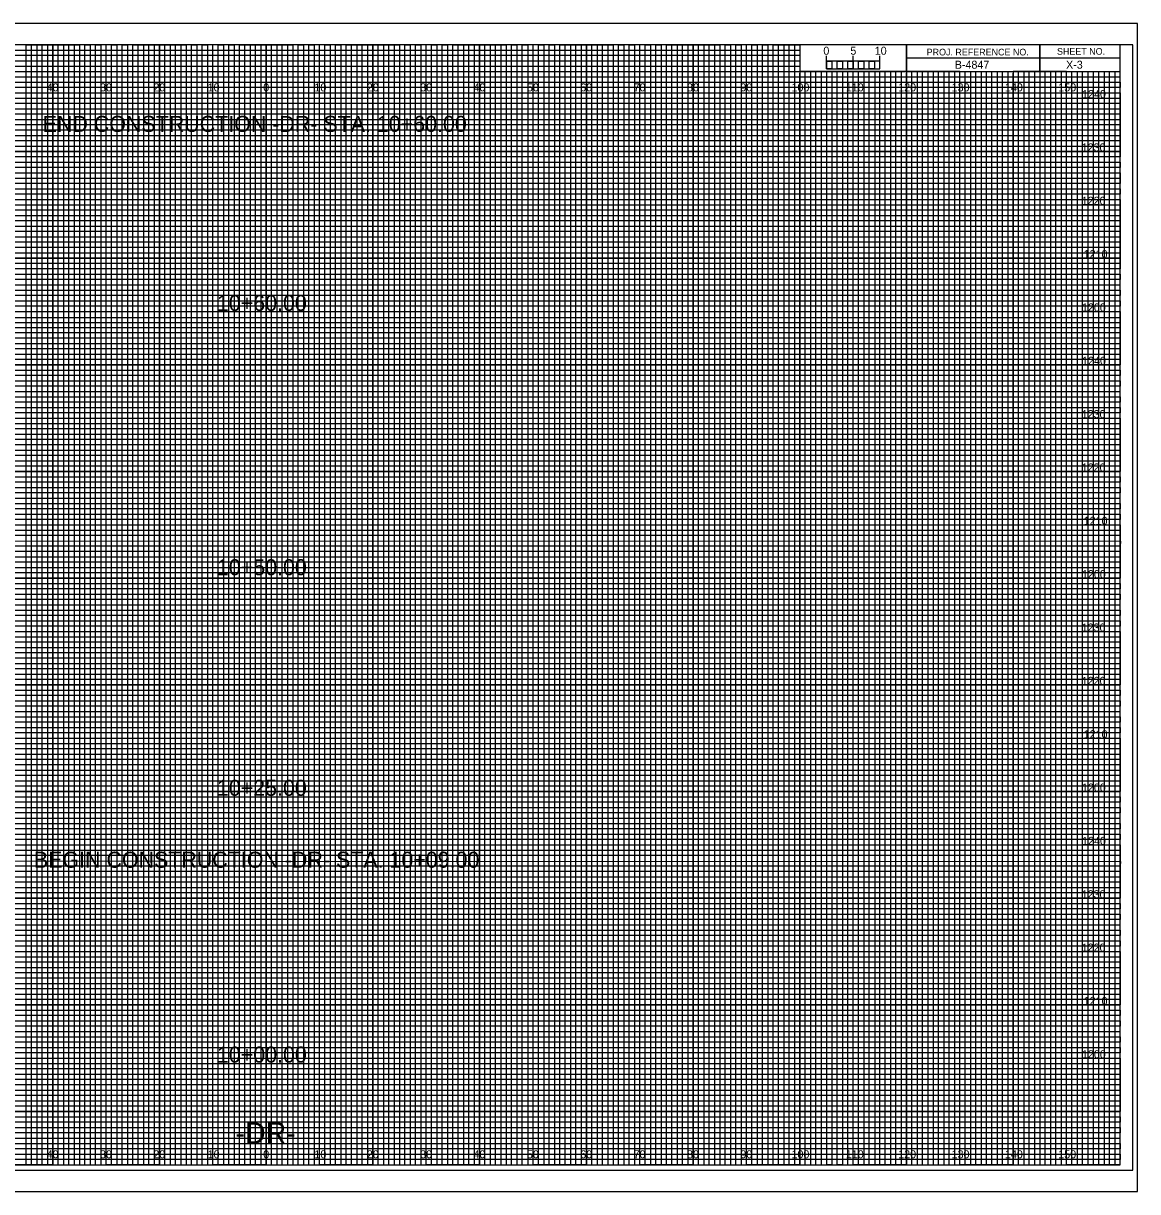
# Model space of a CAD drawing. Extents: x -13 to 323, y -5 to 214.
# Drawn here: x 114.5 to 323.3, y -5 to 214 of the extents above; entities that cross this region are included whole.
import ezdxf

# ---------------------------------------------------------------- set-up
doc = ezdxf.new("R2010")
doc.units = 0
for name, color, linetype in [('Default', 7, 'Continuous'), ('Prop XS Alignment Label', 7, 'Continuous'), ('Prop XS Bar Scale Labels', 7, 'Continuous'), ('Prop XS Elevation Labels', 7, 'Continuous'), ('Prop XS Offset Labels', 7, 'Continuous'), ('Prop XS Project Number', 7, 'Continuous'), ('Prop XS Sheet Number', 7, 'Continuous'), ('Prop XS Station Labels', 7, 'Continuous'), ('Sheet Cross Section CELL', 7, 'Continuous'), ('Sheet Cross Section Grid Major CELL', 7, 'Continuous'), ('Sheet Cross Section Grid Middle CELL', 7, 'Continuous'), ('Sheet Cross Section Grid Minor 1 CELL', 7, 'Continuous'), ('Sheet Cross Section Grid Minor 2 CELL', 7, 'Continuous'), ('Sheet Cross Section Scale CELL', 7, 'Continuous'), ('Sheet Cutting Line CELL', 7, 'Continuous'), ('Sheet DOT Grid CELL', 7, 'Continuous'), ('Sheet Plot Border Inside CELL', 7, 'Continuous'), ('Sheet Plot Border Outside CELL', 7, 'Continuous')]:
    doc.layers.add(name, color=color, linetype=linetype)

msp = doc.modelspace()

# ---------------------------------------------------------------- linework, layer by layer
at = {"layer": 'Sheet Cross Section CELL'}
for p, q in [((305, 210), (305, 205)), ((305, 205), (305, 210)), ((280, 207.5), (280, 205)), ((320, 207.49), (280, 207.49)), ((280, 205), (320, 205))]:
    msp.add_line(p, q, dxfattribs=at)
for points in [[(320, 210), (0, 210), (0, 0), (320, 0)], [(280, 210), (260, 210), (260, 205.03), (280, 205.03)], [(320, 210), (280, 210), (280, 205), (320, 205)]]:
    msp.add_lwpolyline(points, close=True, dxfattribs=at)
at = {"layer": 'Sheet Cross Section Grid Major CELL'}
for p, q in [((130, 210), (120, 210)), ((120, 210), (120, 0)), ((130, 0), (130, 210)), ((150, 210), (140, 210)), ((140, 210), (140, 0)), ((150, 0), (150, 210)), ((170, 210), (160, 210)), ((160, 210), (160, 0)), ((170, 0), (170, 210)), ((190, 210), (180, 210)), ((180, 210), (180, 0)), ((190, 0), (190, 210)), ((210, 210), (200, 210)), ((200, 210), (200, 0)), ((210, 0), (210, 210)), ((230, 210), (220, 210)), ((220, 210), (220, 0)), ((230, 0), (230, 210)), ((250, 210), (240, 210)), ((240, 210), (240, 0)), ((250, 0), (250, 210)), ((260, 210), (260, 0)), ((270, 0), (270, 205)), ((290, 205), (280, 205)), ((280, 205), (280, 0)), ((290, 0), (290, 205)), ((310, 205), (300, 205)), ((300, 205), (300, 0)), ((310, 0), (310, 205)), ((120, 0), (110, 0)), ((140, 0), (130, 0)), ((160, 0), (150, 0)), ((180, 0), (170, 0)), ((200, 0), (190, 0)), ((220, 0), (210, 0)), ((240, 0), (230, 0)), ((260, 0), (250, 0)), ((280, 0), (270, 0)), ((300, 0), (290, 0)), ((320, 0), (310, 0)), ((320, 0), (320, 0))]:
    msp.add_line(p, q, dxfattribs=at)
for points in [[(0, 200), (320, 200), (320, 190), (0, 190)], [(0, 180), (320, 180), (320, 170), (0, 170)], [(0, 160), (320, 160), (320, 150), (0, 150)], [(0, 140), (320, 140), (320, 130), (0, 130)], [(0, 120), (320, 120), (320, 110), (0, 110)], [(0, 100), (320, 100), (320, 90), (0, 90)], [(0, 80), (320, 80), (320, 70), (0, 70)], [(0, 60), (320, 60), (320, 50), (0, 50)], [(0, 40), (320, 40), (320, 30), (0, 30)], [(0, 20), (320, 20), (320, 10), (0, 10)]]:
    msp.add_lwpolyline(points, dxfattribs=at)
at = {"layer": 'Sheet Cross Section Grid Middle CELL'}
for points in [[(105, 0), (115, 0), (115, 210), (125, 210), (125, 0), (135, 0), (135, 210), (145, 210), (145, 0), (155, 0), (155, 210), (165, 210), (165, 0), (175, 0), (175, 210), (185, 210), (185, 0), (195, 0), (195, 210), (205, 210), (205, 0), (215, 0), (215, 210), (225, 210), (225, 0), (235, 0), (235, 210), (245, 210), (245, 0), (255, 0), (255, 210), (259.93, 210), (260, 210), (260, 205), (264.99, 205), (264.99, 0), (275, 0), (275, 205), (285, 205), (285, 0), (295, 0), (295, 205), (305, 205), (305, 0), (315, 0), (315, 205)], [(0, 205), (275, 205)], [(0, 185), (320, 185), (320, 195), (0, 195)], [(0, 165), (320, 165), (320, 175), (0, 175)], [(0, 145), (320, 145), (320, 155), (0, 155)], [(0, 125), (320, 125), (320, 135), (0, 135)], [(0, 105), (320, 105), (320, 115), (0, 115)], [(0, 85), (320, 85), (320, 95), (0, 95)], [(0, 65), (320, 65), (320, 75), (0, 75)], [(0, 45), (320, 45), (320, 55), (0, 55)], [(0, 25), (320, 25), (320, 35), (0, 35)], [(0, 5), (320, 5), (320, 15), (0, 15)]]:
    msp.add_lwpolyline(points, dxfattribs=at)
at = {"layer": 'Sheet Cross Section Grid Minor 1 CELL'}
for p, q in [((0, 209), (260, 209)), ((260, 209), (260, 207.98)), ((260, 207.98), (0, 207.98)), ((0, 207), (260, 207)), ((260, 205.89), (0, 205.89)), ((260, 207), (260, 205.89)), ((0, 204), (320, 204))]:
    msp.add_line(p, q, dxfattribs=at)
for points in [[(0, 203), (270, 203), (320, 203), (320, 202), (0, 202)], [(0, 201), (320, 201), (320, 199), (0, 199)], [(0, 198), (320, 198), (320, 197), (0, 196.98)], [(0, 196), (320, 196), (320, 194), (0, 194)], [(0, 193), (320, 193), (320, 192), (0, 192)], [(0, 191), (320, 191), (320, 189), (0, 189)], [(0, 188), (320, 188), (320, 187), (0, 187)], [(0, 186), (320, 186), (320, 184), (0, 184)], [(0, 183), (320, 183), (320, 182), (0, 182)], [(0, 181), (320, 181), (320, 179), (0, 179)], [(0, 178), (320, 178), (320, 177), (0, 177)], [(0, 176), (320, 176), (320, 173.95), (320, 173), (320, 172), (0, 172)], [(0, 174), (320, 174), (320, 173), (0, 173)], [(0, 171), (320, 171), (320, 169), (0, 169.03)], [(0, 169.03), (320, 169), (320, 168), (0, 168)], [(0, 167), (320, 167), (320, 166), (0, 166)], [(0, 164), (320, 164), (320, 163), (0, 163)], [(0, 162), (320, 162), (320, 161), (0, 161)], [(-0.07, 158.89), (320, 158.89), (320, 157.88), (-0.07, 157.88)], [(0, 157), (320, 157), (320, 156), (0, 156)], [(0, 154), (320, 154), (320, 153), (0, 153)], [(0, 152), (320, 152), (320, 151), (0, 151)], [(0, 149), (320, 149), (320, 148), (0, 148)], [(0, 147), (320, 147), (320, 146), (0, 146)], [(0, 144), (320, 144), (320, 143), (0, 143)], [(0, 142), (320, 142), (320, 141), (0, 141)], [(0, 139), (320, 139), (319.99, 137.98), (0, 138)], [(0, 137), (320, 137), (320, 136), (0, 136)], [(0, 134), (320, 134), (320, 133), (0, 133)], [(0, 132), (320, 132), (320, 131), (0, 131)], [(0, 129), (320, 129), (320, 128), (0, 128)], [(0, 127), (320, 127), (320, 126), (0, 126)], [(0, 124), (320, 124), (320, 123), (0, 123)], [(0, 122), (320, 122), (320, 121), (0, 121)], [(0, 119), (320, 119), (320, 118), (0, 118)], [(0, 116.99), (320.07, 116.91), (320, 116), (0, 116)], [(0, 114), (320, 114), (320, 113), (0, 113)], [(0, 112), (320, 112), (320, 111), (0, 111)], [(0, 109), (320, 109), (320, 108), (0, 108)], [(0, 107), (320, 107), (320, 106), (0, 106)], [(0, 104), (320, 104), (320, 103), (0, 103)], [(0, 102), (320, 102), (320, 101), (0, 101)], [(0, 99), (320, 99), (320, 98), (0, 98)], [(0, 97), (320, 97), (320, 96), (0, 96)], [(0, 94), (320, 94), (320, 93), (0, 93)], [(0, 92), (320, 92), (320, 91), (0, 91)], [(0, 89), (320, 89), (320, 88), (0, 88)], [(0, 87), (320, 87), (320, 86), (0, 86)], [(0, 84), (320, 84), (320, 83), (0, 83)], [(0, 82), (320, 82), (320, 81), (0, 81)], [(0, 79), (320, 79), (319.99, 77.98), (0, 78)], [(0, 77), (320, 77), (320, 76), (0, 76)], [(0, 74), (320, 74), (320, 73), (0, 73)], [(0, 72), (320, 72), (320, 71), (0, 71)], [(0, 69), (320, 69), (320, 68), (0, 68)], [(0, 67), (320, 67), (320, 66), (0, 66)], [(0, 64), (320, 64), (320, 63), (0, 63)], [(0, 62), (320, 62), (320, 61), (0, 61)], [(0, 59), (320, 59), (320, 58), (0, 58)], [(0, 56.99), (320.07, 56.91), (320, 56), (0, 56)], [(0, 54), (320, 54), (320, 53), (0, 53)], [(0, 52), (320, 52), (320, 51), (0, 51)], [(0, 49), (320, 49), (320, 48), (0, 48)], [(0, 47), (320, 47), (320, 46), (0, 46)], [(0, 44), (320, 44), (320, 43), (0, 43)], [(0, 42), (320, 42), (320, 41), (0, 41)], [(0, 39), (320, 39), (320, 38), (0, 38)], [(0, 37), (320, 37), (320, 36), (0, 36)], [(0, 34), (320, 34), (320, 33), (0, 33)], [(0, 32), (320, 32), (320, 31), (0, 31)], [(0, 29), (320, 29), (320, 28), (0, 28)], [(0, 27), (320, 27), (320, 26), (0, 26)], [(0, 24), (320, 24), (320, 23), (0, 23)], [(0, 22), (320, 22), (320, 21), (0, 21)], [(0, 19), (320, 19), (320, 18), (0, 18)], [(0, 17), (320, 17), (320, 16), (0, 16)], [(0, 14), (320, 14), (320, 13), (0, 13)], [(0, 12), (320, 12), (320, 11), (0, 11)], [(0, 9), (320, 9), (320, 8), (0, 8)], [(0, 7), (320, 7), (320, 6), (0, 6)], [(0, 4), (320, 4), (320, 3), (0, 3)], [(0, 2), (320, 2), (320, 1), (0, 1)]]:
    msp.add_lwpolyline(points, dxfattribs=at)
at = {"layer": 'Sheet Cross Section Grid Minor 2 CELL'}
for p, q in [((267, 205), (266.01, 205)), ((266.01, 205), (266.01, 0)), ((267, 0), (267, 205)), ((269, 205), (268, 205)), ((268, 205), (268, 0)), ((269, 0), (269, 205)), ((266.01, 0), (265, 0)), ((268, 0), (267, 0))]:
    msp.add_line(p, q, dxfattribs=at)
for points in [[(115, 0), (116, 0), (116, 210), (117, 210), (117, 0)], [(117, 0), (118, 0), (118, 210), (119, 210), (119, 0)], [(120, 0), (121, 0), (121, 210), (122, 210), (122, 0)], [(122, 0), (123, 0), (123, 210), (124, 210), (124, 0)], [(125, 0), (126, 0), (126, 210), (127, 210), (127, 0)], [(127, 0), (128, 0), (128, 210), (129, 210), (129, 0)], [(130, 0), (131, 0), (131, 210), (132, 210), (132, 0)], [(132, 0), (133, 0), (133, 210), (134, 210), (134, 0)], [(135, 0), (136, 0), (136, 210), (137, 210), (137, 0)], [(137, 0), (138, 0), (138, 210), (139, 210), (139, 0)], [(140, 0), (141, 0), (141, 210), (142, 210), (142, 0)], [(142, 0), (143, 0), (143, 210), (144, 210), (144, 0)], [(145, 0), (146, 0), (146, 210), (147, 210), (147, 0)], [(147, 0), (148, 0), (148, 210), (149, 210), (149, 0)], [(150, 0), (151, 0), (151, 210), (152, 210), (152, 0)], [(152, 0), (153, 0), (153, 210), (154, 210), (154, 0)], [(155, 0), (156, 0), (156, 210), (157, 210), (157, 0)], [(157, 0), (158, 0), (158, 210), (159, 210), (159, 0)], [(160, 0), (161, 0), (161, 210), (162, 210), (162, 0)], [(162, 0), (163, 0), (163, 210), (164, 210), (164, 0)], [(165, 0), (166, 0), (166, 210), (167, 210), (167, 0)], [(167, 0), (168, 0), (168, 210), (169, 210), (169, 0)], [(170, 0), (171, 0), (171, 210), (172, 210), (172, 0)], [(172, 0), (173, 0), (173, 210), (174, 210), (174, 0)], [(175, 0), (176, 0), (176, 210), (177, 210), (177, 0)], [(177, 0), (178, 0), (178, 210), (179, 210), (179, 0)], [(180, 0), (181, 0), (181, 210), (182, 210), (182, 0)], [(182, 0), (183, 0), (183, 210), (184, 210), (184, 0)], [(185, 0), (186, 0), (186, 210), (187, 210), (187, 0)], [(187, 0), (188, 0), (188, 210), (189, 210), (189, 0)], [(190, 0), (191, 0), (191, 210), (192, 210), (192, 0)], [(192, 0), (193, 0), (193, 210), (194, 210), (194, 0)], [(195, 0), (196, 0), (196, 210), (197, 210), (197, 0)], [(197, 0), (198, 0), (198, 210), (199, 210), (199, 0)], [(200, 0), (201, 0), (201, 210), (202, 210), (202, 0)], [(202, 0), (203, 0), (203, 210), (204, 210), (204, 0)], [(205, 0), (206, 0), (206, 210), (207, 210), (207, 0)], [(207, 0), (208, 0), (208, 210), (209, 210), (209, 0)], [(210, 0), (211, 0), (211, 210), (212, 210), (212, 0)], [(212, 0), (213, 0), (213, 210), (214, 210), (214, 0)], [(215, 0), (216, 0), (216, 210), (217, 210), (217, 0)], [(217, 0), (218, 0), (218, 210), (219, 210), (219, 0)], [(220, 0), (221, 0), (221, 210), (222, 210), (222, 0)], [(222, 0), (223, 0), (223, 210), (224, 210), (224, 0)], [(225, 0), (226, 0), (226, 210), (227, 210), (227, 0)], [(227, 0), (228, 0), (228, 210), (229, 210), (229, 0)], [(230, 0), (231, 0), (231, 210), (232, 210), (232, 0)], [(232, 0), (233, 0), (233, 210), (234, 210), (234, 0)], [(235, 0), (236, 0), (236, 210), (237, 210), (237, 0)], [(237, 0), (238, 0), (238, 210), (239, 210), (239, 0)], [(240, 0), (241, 0), (241, 210), (242, 210), (242, 0)], [(242, 0), (243, 0), (243, 210), (244, 210), (244, 0)], [(245, 0), (246, 0), (246, 210), (247, 210), (247, 0)], [(247, 0), (248, 0), (248, 210), (249, 210), (249, 0)], [(250, 0), (251, 0), (251, 210), (252, 210), (252, 0)], [(252, 0), (253, 0), (253, 210), (254, 210), (254, 0)], [(255, 0), (256, 0), (256, 210), (257, 210), (257, 0)], [(257, 0), (258, 0), (258, 210), (259, 210), (259, 0)], [(260, 0), (261, 0), (261, 205), (262.02, 205), (262.02, 0)], [(262, 0), (263, 0), (263, 205), (263.99, 205), (263.99, 0)], [(270, 0), (270.98, 0), (270.98, 205), (272, 205), (272, 0)], [(272, 0), (273, 0), (273, 205), (274.05, 205), (274.05, 0)], [(275, 0), (276, 0), (276, 205), (277, 205), (277, 0)], [(277, 0), (278, 0), (278, 205), (279, 205), (279, 0)], [(280, 0), (281, 0), (281, 205), (282, 205), (282, 0)], [(282, 0), (283, 0), (283, 205), (284, 205), (284, 0)], [(285, 0), (286, 0), (286, 205), (287, 205), (287, 0)], [(287, 0), (288, 0), (288, 205), (289, 205), (289, 0)], [(290, 0), (291, 0), (291, 205), (292, 205), (292, 0)], [(292, 0), (293, 0), (293, 205), (294, 205), (294, 0)], [(295, 0), (296, 0), (296, 205), (297, 205), (297, 0)], [(297, 0), (298, 0), (298, 205), (299, 205), (299, 0)], [(300, 0), (301, 0), (301, 205), (302, 205), (302, 0)], [(302, 0), (303, 0), (303, 205), (304, 205), (304, 0)], [(305, 0), (306, 0), (306, 205), (307, 205), (307, 0)], [(307, 0), (308, 0), (308, 205), (309, 205), (309, 0)], [(310, 0), (311, 0), (311, 205), (312, 205), (312, 0)], [(312, 0), (313, 0), (313, 205), (314, 205), (314, 0)], [(315, 0), (316, 0), (316, 205), (317, 205), (317, 0)], [(317, 0), (318, 0), (318, 205), (319, 205), (319, 0)]]:
    msp.add_lwpolyline(points, dxfattribs=at)
at = {"layer": 'Sheet Cross Section Scale CELL'}
for p, q in [((265, 205.49), (265, 207.9)), ((265, 206.9), (265, 207.9)), ((270, 205.49), (270, 207.9)), ((275, 205.49), (275, 207.9)), ((275, 206.9), (275, 207.9))]:
    msp.add_line(p, q, dxfattribs=at)
for points in [[(275, 206.9), (265, 206.9), (265, 205.49), (275, 205.49)], [(265, 206.9), (266, 206.9), (266, 205.49), (265, 205.49)], [(267, 206.9), (268, 206.9), (268, 205.49), (267, 205.49)], [(269, 206.9), (270, 206.9), (270, 205.49), (269, 205.49)], [(271, 206.9), (272, 206.9), (272, 205.49), (271, 205.49)], [(273, 206.9), (274, 206.9), (274, 205.49), (273, 205.49)]]:
    msp.add_lwpolyline(points, close=True, dxfattribs=at)
at = {"layer": 'Sheet Cutting Line CELL'}
for p, q in [((323.3, 214), (-13.4, 214)), ((-13.4, -5), (323.3, -5))]:
    msp.add_line(p, q, dxfattribs=at)
at = {"layer": 'Sheet DOT Grid CELL'}
for p, q in [((120, 0), (120, 210)), ((130, 0), (130, 210)), ((140, 0), (140, 210)), ((150, 0), (150, 210)), ((160, 0), (160, 210)), ((170, 0), (170, 210)), ((180, 0), (180, 210)), ((190, 0), (190, 210)), ((200, 0), (200, 210)), ((210, 0), (210, 210)), ((220, 0), (220, 210)), ((230, 0), (230, 210)), ((240, 0), (240, 210)), ((250, 0), (250, 210)), ((260, 0), (260, 204.69)), ((270, 0), (270, 204.69)), ((280, 0), (280, 204.69)), ((290, 0), (290, 204.69)), ((300, 0), (300, 204.69)), ((310, 0), (310, 204.69)), ((0, 200), (320, 200)), ((0, 190), (320, 190)), ((0, 180), (320, 180)), ((0, 170), (320, 170)), ((0, 160), (320, 160)), ((0, 150), (320, 150)), ((0, 140), (320, 140)), ((0, 130), (320, 130)), ((0, 120), (320, 120)), ((0, 110), (320, 110)), ((0, 100), (320, 100)), ((0, 90), (320, 90)), ((0, 80), (320, 80)), ((0, 70), (320, 70)), ((0, 60), (320, 60)), ((0, 50), (320, 50)), ((0, 40), (320, 40)), ((0, 30), (320, 30)), ((0, 20), (320, 20)), ((0, 10), (320, 10))]:
    msp.add_line(p, q, dxfattribs=at)
at = {"layer": 'Sheet Plot Border Inside CELL'}
msp.add_lwpolyline([(-10.8, -1), (322.4, -1), (322.4, 210), (-10.8, 210)], close=True, dxfattribs=at)
at = {"layer": 'Sheet Plot Border Outside CELL'}
msp.add_lwpolyline([(-13.4, -5), (323.3, -5), (323.3, 214), (-13.4, 214)], close=True, dxfattribs=at)

# ---------------------------------------------------------------- texts
at = {"layer": 'Default'}
for s, p in [('END CONSTRUCTION -DR- STA. 10+60.00', (118.12, 193.66)), ('BEGIN CONSTRUCTION -DR- STA. 10+09.00', (116.47, 55.72))]:
    msp.add_text(s, height=3, dxfattribs=at).set_placement(p)
at = {"layer": 'Prop XS Alignment Label'}
msp.add_text('-DR-', height=4, dxfattribs=at).set_placement((154.25, 4))
at = {"layer": 'Prop XS Bar Scale Labels'}
for s, p in [('5', (269.47, 208.12)), ('10', (274.04, 208.12))]:
    msp.add_text(s, height=1.5, dxfattribs=at).set_placement(p)
at = {"layer": 'Prop XS Elevation Labels'}
for s, p in [('1240', (312.9, 200)), ('1230', (312.82, 190)), ('1220', (312.83, 180)), ('1210', (313.2, 170)), ('1200', (312.87, 160)), ('1240', (312.9, 150)), ('1230', (312.82, 140)), ('1220', (312.83, 130)), ('1210', (313.2, 120)), ('1200', (312.87, 110)), ('1230', (312.82, 100)), ('1220', (312.83, 90)), ('1210', (313.2, 80)), ('1200', (312.87, 70)), ('1240', (312.9, 60)), ('1230', (312.82, 50)), ('1220', (312.83, 40)), ('1210', (313.2, 30)), ('1200', (312.87, 20))]:
    msp.add_text(s, height=1.5, dxfattribs=at).set_placement(p)
at = {"layer": 'Prop XS Offset Labels'}
for s, p in [('40', (118.86, 201.25)), ('30', (128.86, 201.25)), ('20', (138.86, 201.25)), ('10', (149.04, 201.25)), ('0', (159.45, 201.25)), ('0', (159.45, 201.25)), ('10', (169.04, 201.25)), ('20', (178.86, 201.25)), ('30', (188.86, 201.25)), ('40', (198.86, 201.25)), ('50', (208.86, 201.25)), ('60', (218.86, 201.25)), ('70', (228.86, 201.25)), ('80', (238.86, 201.25)), ('90', (248.86, 201.25)), ('100', (258.44, 201.25)), ('110', (268.62, 201.25)), ('120', (278.44, 201.25)), ('130', (288.44, 201.25)), ('140', (298.44, 201.25)), ('150', (308.44, 201.25)), ('40', (118.86, 1.25)), ('30', (128.86, 1.25)), ('20', (138.86, 1.25)), ('10', (149.04, 1.25)), ('0', (159.45, 1.25)), ('0', (159.45, 1.25)), ('10', (169.04, 1.25)), ('20', (178.86, 1.25)), ('30', (188.86, 1.25)), ('40', (198.86, 1.25)), ('50', (208.86, 1.25)), ('60', (218.86, 1.25)), ('70', (228.86, 1.25)), ('80', (238.86, 1.25)), ('90', (248.86, 1.25)), ('100', (258.44, 1.25)), ('110', (268.62, 1.25)), ('120', (278.44, 1.25)), ('130', (288.44, 1.25)), ('140', (298.44, 1.25)), ('150', (308.44, 1.25))]:
    msp.add_text(s, height=1.5, dxfattribs=at).set_placement(p)
at = {"layer": 'Prop XS Project Number'}
msp.add_text('B-4847', height=1.5, dxfattribs=at).set_placement((289.04, 205.5))
at = {"layer": 'Prop XS Sheet Number'}
msp.add_text('X-3', height=1.5, dxfattribs=at).set_placement((309.89, 205.5))
at = {"layer": 'Prop XS Station Labels'}
for s, p in [('10+60.00', (150.77, 160.09)), ('10+50.00', (150.77, 110.55)), ('10+25.00', (150.77, 69.2)), ('10+00.00', (150.77, 19.19))]:
    msp.add_text(s, height=3, dxfattribs=at).set_placement(p)
at = {"layer": 'Sheet Cross Section CELL'}
for s, p in [('PROJ. REFERENCE NO.', (283.77, 207.99)), ('SHEET NO.', (308.19, 208.12))]:
    msp.add_text(s, height=1.25, dxfattribs=at).set_placement(p)
at = {"layer": 'Sheet Cross Section Scale CELL'}
msp.add_text('0', height=1.5, dxfattribs=at).set_placement((264.41, 208.12))

doc.saveas('drawing.dxf')
